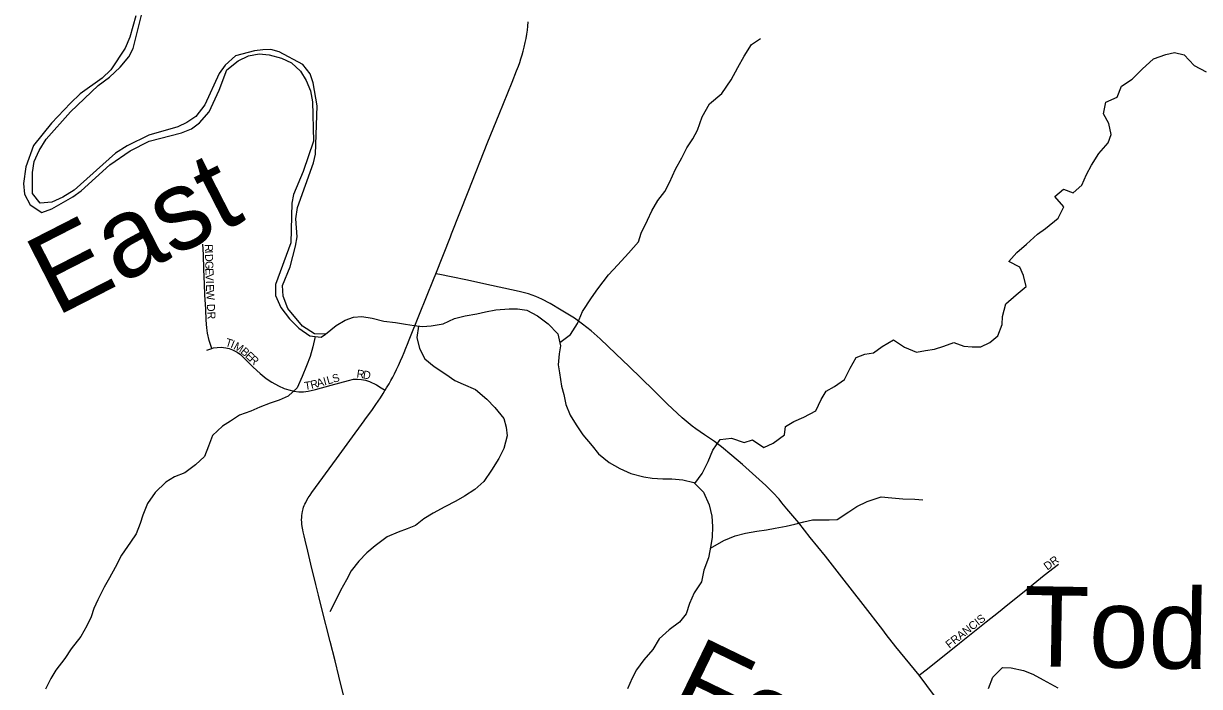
# Model space of a CAD drawing. Extents: x 1442749 to 1756758, y 235267 to 677782.
# Drawn here: x 1558820 to 1566168, y 496421 to 500562 of the extents above; entities that cross this region are included whole.
import ezdxf

# ---------------------------------------------------------------- set-up
doc = ezdxf.new("R2010")
doc.units = 0
for name, color, linetype in [('GM_X_Major_River', 7, 'Continuous'), ('GM_X_Minor_River', 7, 'Continuous'), ('GM_X_Minor_River_Text', 7, 'Continuous'), ('GM_X_State_Route', 7, 'Continuous'), ('GM_X_Township_Road', 7, 'Continuous'), ('GM_X_Township_Subdivision', 7, 'Continuous'), ('GM_X_Township_Subdivision_Text', 7, 'Continuous')]:
    doc.layers.add(name, color=color, linetype=linetype)

msp = doc.modelspace()

# ---------------------------------------------------------------- linework, layer by layer
at = {"layer": 'GM_X_Major_River'}
for points in [[(1559951.9, 500053.5), (1559896.8, 499982), (1559840.2, 499942.7), (1559783.7, 499917.4), (1559602.8, 499863.8), (1559467.7, 499797.4), (1559394.9, 499752.3), (1559135.3, 499521.3), (1559064.6, 499476.2), (1558996.1, 499445), (1558923.9, 499440), (1558874.8, 499500.8), (1558874.7, 499631.1), (1558885.6, 499699.1), (1558916.7, 499768.8), (1558961.8, 499840.4), (1559112.4, 500010.7), (1559287, 500174.7), (1559355.8, 500225.9), (1559422.8, 500289.1), (1559477.8, 500354.5), (1559504.5, 500406.3), (1559572.6, 500680)], [(1559521.5, 500610.5), (1559483.5, 500476.7)], [(1559483.5, 500476.7), (1559454.5, 500407), (1559364.5, 500271.9), (1559311.7, 500220.5), (1559174.1, 500122.1), (1559113.2, 500064.8), (1558995.3, 499940.1)], [(1558995.3, 499940.1), (1558881.1, 499799.3), (1558833.1, 499665.7), (1558819.6, 499561.7), (1558826.6, 499495.4), (1558861.7, 499428.8), (1558933.1, 499381.7), (1558995.5, 499404.9), (1559128.7, 499479.3), (1559179.3, 499516.7), (1559359.8, 499678.6), (1559485.2, 499767.1), (1559604.2, 499827.6), (1559807.2, 499879), (1559869.6, 499904.2), (1559920.2, 499941.6), (1559979.3, 500011), (1560041.3, 500144.5), (1560089.2, 500272.1), (1560160.1, 500329.3), (1560224.6, 500360.5), (1560292.8, 500371.6), (1560354.8, 500366.7), (1560430.6, 500345.7), (1560494.2, 500316.7), (1560549.5, 500263.9), (1560586.7, 500205.2), (1560611.8, 500140.8), (1560624.8, 500072.4), (1560631.3, 499827.8), (1560566.5, 499638.3), (1560506.3, 499492.8), (1560495.5, 499438.8), (1560489.9, 499192.3), (1560394, 498931), (1560395, 498862.8), (1560428, 498788.2), (1560481, 498717.4), (1560540.2, 498658.4), (1560609.6, 498611.4), (1560641.9, 498607.3), (1560679.5, 498602.4), (1560705.8, 498622.1)], [(1560365.3, 500398.6), (1560315.2, 500397.3), (1560263.1, 500392), (1560144.5, 500359.5), (1560079.6, 500302.3), (1560042.8, 500248.7), (1559951.9, 500053.5)], [(1560705.8, 498622.1), (1560637.8, 498623), (1560562.4, 498672.2), (1560471.9, 498781.6), (1560443, 498858.2), (1560438, 498924.4), (1560485.7, 499042), (1560519.6, 499171.9), (1560528.5, 499229.9), (1560522.1, 499342.2), (1560531.1, 499412.2), (1560631.3, 499691.5), (1560644.1, 499745.5), (1560654.5, 500048), (1560630.5, 500190.6), (1560611.3, 500247), (1560564.2, 500305.8), (1560417.2, 500385.9), (1560365.3, 500398.6)]]:
    msp.add_lwpolyline(points, dxfattribs=at)
at = {"layer": 'GM_X_Minor_River'}
for points in [[(1562170.2, 498568.5), (1562237.3, 498619.5), (1562280.4, 498687.1), (1562311.5, 498762.8), (1562368.8, 498848.2), (1562407.6, 498903.8), (1562475, 498991.1), (1562534, 499054.5), (1562599.1, 499127.7), (1562662.2, 499199), (1562679, 499252.9), (1562718.2, 499332.6), (1562745.1, 499392.4), (1562784, 499456), (1562826.9, 499513.5), (1562855.8, 499569.3), (1562893, 499653), (1562934.1, 499722.5), (1562965, 499786.3), (1563001.9, 499841.9), (1563030.7, 499895.6), (1563059.9, 499979.4), (1563105.2, 500061), (1563184.1, 500124.1), (1563241.4, 500209.5), (1563282.6, 500287.1), (1563321.7, 500358.7), (1563368.8, 500430.2), (1563425.4, 500467.6)], [(1563014.6, 497688.9), (1563059.5, 497750.5), (1563098.7, 497826.1), (1563127.8, 497897.9), (1563172.8, 497963.4), (1563243, 497972.5), (1563322.6, 497945.3), (1563374.9, 497960.7), (1563446.3, 497913.6), (1563502.8, 497940.9), (1563575.6, 497992), (1563580.3, 498044.1), (1563632.8, 498075.5), (1563695.3, 498102.7), (1563769.9, 498141.8), (1563803, 498213.5), (1563835.8, 498265.1), (1563886.3, 498294.5), (1563949, 498337.8), (1563984, 498409.5), (1564023, 498475.1), (1564077.4, 498496.4), (1564131.6, 498505.7), (1564184.2, 498545), (1564254.9, 498586.2), (1564324.3, 498541.1), (1564399.9, 498508), (1564456.1, 498519.3), (1564512.3, 498528.6), (1564570.6, 498545.8), (1564633, 498569), (1564694.7, 498546.1), (1564746.7, 498541.4), (1564800.8, 498542.7), (1564857.2, 498570), (1564907.9, 498611.4), (1564934.9, 498681.2), (1564937.7, 498731.3), (1564956.9, 498811.2), (1565021.7, 498866.4), (1565084.6, 498919.7), (1565067.5, 498988.1), (1565044.3, 499040.5), (1564976.7, 499075.5), (1565025.6, 499131), (1565086.4, 499184.3), (1565155.4, 499245.5), (1565205.9, 499280.9), (1565285, 499345.9), (1565320, 499417.6), (1565262.9, 499480.5), (1565317.6, 499527.9), (1565379.4, 499505), (1565432.1, 499552.4), (1565461.1, 499618.2), (1565494, 499677.8), (1565539.1, 499749.4), (1565598.1, 499816.8), (1565614.9, 499868.6), (1565601.9, 499937), (1565568.7, 499997.5), (1565581.8, 500071.5), (1565654.3, 500102.6), (1565681.3, 500170.4), (1565748, 500213.6), (1565809, 500276.9), (1565880, 500342.1), (1565956.5, 500369.1), (1566010.7, 500380.4), (1566072.5, 500365.5), (1566133.6, 500298.6), (1566209.1, 500259.5)], [(1560705.8, 498622.1), (1560772.7, 498675.3), (1560829.2, 498708.6), (1560881.5, 498728), (1560933.7, 498731.3), (1560997.6, 498722.4), (1561071.4, 498703.4), (1561143.3, 498694.4), (1561207.2, 498683.5), (1561261.2, 498674.8), (1561313.1, 498670), (1561367.3, 498673.3), (1561441.5, 498686.4), (1561512.1, 498719.5), (1561578.4, 498736.6), (1561652.6, 498747.6), (1561706.9, 498761), (1561771.1, 498774.1), (1561853.3, 498779), (1561905.3, 498780.3), (1561965.3, 498771.5), (1562030.8, 498736.5), (1562098.2, 498685.5), (1562159.3, 498622.5), (1562174.2, 498548.2), (1562167.5, 498498.1), (1562160.5, 498430.1), (1562167.8, 498379.9), (1562180.6, 498297.5), (1562195.9, 498245.2), (1562209, 498182.9), (1562236, 498116.4), (1562273.2, 498055.7), (1562314.3, 497993), (1562373.4, 497924.1), (1562412.7, 497873.5), (1562480, 497820.4), (1562545.5, 497781.5), (1562615.1, 497750.5), (1562694.9, 497731.3), (1562746.8, 497722.6), (1562814.8, 497717.7), (1562870.9, 497716.9), (1562938.9, 497712), (1563008.7, 497695), (1563067.9, 497634.1), (1563104.8, 497555.4), (1563119.7, 497485.1), (1563124.8, 497420.8), (1563121.8, 497352.7), (1563115.1, 497300.7), (1563100, 497224.8), (1563070.8, 497147), (1563055.7, 497075), (1563010.7, 497005.5), (1562981.7, 496939.7), (1562960.7, 496873.8), (1562917.9, 496822.3), (1562853.2, 496775.1), (1562792.3, 496717.8), (1562751.3, 496652.2), (1562696.3, 496586.8), (1562649.3, 496525.3), (1562622.6, 496473.5), (1562593.6, 496405.8)], [(1561287.6, 498672.4), (1561278.1, 498600.4), (1561293.1, 498532), (1561328.2, 498467.4), (1561385.6, 498420.5), (1561459, 498371.4), (1561514.5, 498332.6), (1561566.2, 498309.8), (1561643.8, 498276.7), (1561714.9, 498215.6), (1561764.2, 498162.8), (1561821.3, 498093.9), (1561834.5, 498039.6), (1561841.8, 497987.4), (1561820.6, 497907.5), (1561789.6, 497843.8), (1561744.5, 497772.2), (1561695.5, 497700.7), (1561640.7, 497651.4), (1561576, 497610.1), (1561521.5, 497578.8), (1561452.9, 497543.7), (1561378.3, 497502.6), (1561321.7, 497467.3), (1561269, 497425.9), (1561216.7, 497404.5), (1561160.3, 497385.3), (1561091.8, 497356.1), (1561016.9, 497299), (1560964.3, 497255.6), (1560915.5, 497204.2), (1560866.5, 497142.7), (1560837.7, 497086.9), (1560800.7, 497021.3), (1560769.7, 496955.6), (1560732.7, 496887.9)], [(1560641.9, 498607.3), (1560626.6, 498543), (1560611.7, 498481.1), (1560588.8, 498423.3), (1560559.8, 498357.5), (1560528.8, 498285.8), (1560474, 498234.4), (1560417.5, 498209.1), (1560361.2, 498189.8), (1560296.8, 498164.6), (1560240.4, 498141.3), (1560169.9, 498116.2), (1560113.4, 498078.9), (1560062.8, 498047.5), (1559999.9, 497988.2), (1559974.9, 497922.4), (1559950, 497856.6), (1559893.2, 497805.3), (1559828.4, 497756), (1559763.9, 497730.8), (1559709.4, 497697.5), (1559642.4, 497632.3), (1559595.3, 497562.8), (1559564.3, 497491), (1559547.5, 497439.1), (1559524.5, 497375.3), (1559487.7, 497321.7), (1559432.5, 497240.2), (1559391.3, 497164.6), (1559356.4, 497099), (1559323.5, 497041.3), (1559284.3, 496961.6), (1559259.5, 496907.8), (1559242.7, 496856), (1559215.9, 496800.2), (1559176.9, 496732.6), (1559117.7, 496655.2), (1559076.8, 496595.6), (1559021.6, 496522.2), (1558990.9, 496470.5), (1558955.9, 496404.8)], [(1563112.1, 497285.6), (1563195.6, 497331.7), (1563266.1, 497362.8), (1563330.4, 497378), (1563402.7, 497391), (1563462.9, 497400.2), (1563517.1, 497409.5), (1563585.3, 497422.6), (1563639.5, 497433.9), (1563695.8, 497449.2), (1563750.1, 497462.5), (1563854.1, 497461.1), (1563904.2, 497464.4), (1563977, 497511.5), (1564027.5, 497544.9), (1564092, 497576.1), (1564178.6, 497605), (1564244.5, 497598.1), (1564314.5, 497593.2), (1564388.5, 497590.2), (1564438.6, 497587.5)], [(1564849.8, 496407.3), (1564876.9, 496479.1), (1564937.8, 496538.4), (1564991.9, 496537.6), (1565067.7, 496520.6), (1565127.4, 496497.7), (1565191, 496462.8), (1565282.3, 496411.4)]]:
    msp.add_lwpolyline(points, dxfattribs=at)
at = {"layer": 'GM_X_State_Route'}
for points in [[(1561486.7, 499229.5), (1561494.5, 499249.1), (1561598.3, 499511.5), (1561721.6, 499822.5), (1561792.2, 499995.7), (1561872.6, 500195.6), (1561900.4, 500265.5), (1561911.7, 500295), (1561920.4, 500319.3), (1561927.3, 500340.6), (1561934.7, 500365.8), (1561941.2, 500389.2), (1561947.7, 500414.8), (1561954.7, 500443), (1561959.9, 500468.2), (1561964.7, 500495.9), (1561968.1, 500521.1), (1561970.7, 500545), (1561973.3, 500571.9)], [(1560948.8, 498080), (1560957.3, 498091.6), (1560976.9, 498119.2), (1560999.8, 498151.3), (1561021.7, 498182.8), (1561035.9, 498203.7), (1561049.3, 498223.4), (1561067.1, 498251.3), (1561077.8, 498269), (1561079.5, 498271.7), (1561088.3, 498286.3), (1561104, 498311.9), (1561115.7, 498332.8), (1561126.5, 498352.7), (1561137.8, 498374.4), (1561150.5, 498400.6), (1561162.1, 498426.1), (1561175.2, 498455.2), (1561187, 498481.5), (1561197.3, 498506.4), (1561209, 498534.6), (1561219, 498559.8), (1561228.9, 498585), (1561293.2, 498746.5), (1561380.7, 498962.5), (1561395.1, 498998.9), (1561486.7, 499229.5)], [(1560860.1, 496198.6), (1560789.6, 496485.4), (1560766.5, 496581), (1560736, 496701.9), (1560684.2, 496905), (1560663, 496991.1), (1560646.5, 497057.9), (1560615.5, 497185.3), (1560595.9, 497265), (1560578.5, 497335), (1560572.5, 497361.4), (1560566.7, 497387), (1560564, 497400.1), (1560562.3, 497410), (1560560.5, 497421.1), (1560558.9, 497434.3), (1560558, 497446.7), (1560557.5, 497462.6), (1560557.9, 497475.6), (1560558.9, 497488.6), (1560560.2, 497501.1), (1560562.3, 497513.8), (1560566.1, 497529.4), (1560569.7, 497540.2), (1560573.8, 497550.3), (1560577.9, 497560.2), (1560583, 497570.8), (1560590.9, 497584.9), (1560599, 497599), (1560609.8, 497615.2), (1560620.7, 497631.6), (1560774.7, 497843.4), (1560858.5, 497956.6), (1560948.8, 498080)]]:
    msp.add_lwpolyline(points, dxfattribs=at)
at = {"layer": 'GM_X_Township_Road'}
for points in [[(1564415.2, 496491.2), (1564271.3, 496669.1), (1564210.3, 496746.3), (1564188.1, 496774.4), (1564065.5, 496933.8), (1563932.4, 497104.6), (1563830.6, 497233.9), (1563736, 497350.5), (1563664.4, 497442.3), (1563590.1, 497530.4), (1563558, 497568), (1563540.5, 497590), (1563502.1, 497633.4), (1563457.8, 497676.8), (1563396.5, 497733.2), (1563313.1, 497807.1), (1563246.6, 497863.1), (1563181.7, 497916.8), (1563156.5, 497936.1), (1563137.2, 497950.2), (1563073.9, 497993.1), (1563019.7, 498029.6), (1562997.1, 498047.3), (1562935.5, 498098), (1562844.5, 498183.3), (1562755.7, 498270.8), (1562603, 498419.6), (1562520.3, 498499.2), (1562422.9, 498591.9), (1562366.7, 498642), (1562312.7, 498684.5), (1562262, 498720.4), (1562179.8, 498770.5), (1562111.4, 498812.8), (1562059.3, 498840.2), (1562020.4, 498857), (1561974.1, 498872.8), (1561917.3, 498888.2), (1561696.7, 498936.8), (1561594, 498958.3), (1561491.1, 498978.7), (1561421.3, 498993.4), (1561395.1, 498998.9)], [(1564897.4, 495921.6), (1564871.2, 495939.5), (1564808.7, 495986.9), (1564780.1, 496008.9), (1564698.1, 496074.6), (1564679.1, 496093.2), (1564660.2, 496116.2), (1564636.2, 496151.8), (1564612.4, 496194.9), (1564578.2, 496258.2), (1564543, 496317.1), (1564511.8, 496363), (1564415.2, 496491.2)]]:
    msp.add_lwpolyline(points, dxfattribs=at)
at = {"layer": 'GM_X_Township_Subdivision'}
for points in [[(1559996.2, 498531.9), (1559987.6, 498557.1), (1559978.8, 498582.7), (1559969.8, 498627.2), (1559964.8, 498660), (1559961.6, 498709.4), (1559959.2, 498778.4), (1559953.3, 498866.9), (1559949.8, 498935.7), (1559946.6, 499025.5), (1559943.3, 499120), (1559940.4, 499183.2)], [(1559965.1, 498520.7), (1559983, 498528), (1559996.2, 498531.9)], [(1559996.2, 498531.9), (1560007.5, 498535.2), (1560029.5, 498538.7), (1560055, 498539.7), (1560083.6, 498536.8), (1560105.2, 498531.7), (1560126, 498523.5), (1560154.3, 498508.5), (1560175, 498493.7), (1560203.1, 498467), (1560254.2, 498416.2), (1560297.5, 498375.9), (1560336.1, 498345.1), (1560371.7, 498321.3), (1560412.1, 498298.8), (1560448.4, 498282.5), (1560476.8, 498272.9), (1560509.1, 498265.3), (1560539, 498261.6), (1560569.1, 498261.7), (1560598.8, 498265.2), (1560644.1, 498275.1), (1560742.1, 498302.8), (1560849.3, 498333), (1560880.7, 498339.6), (1560906.2, 498341.2), (1560931.7, 498339.2), (1560956.7, 498333.9), (1560980.8, 498325.5), (1561024.6, 498304), (1561055.1, 498286), (1561079.5, 498271.7)], [(1564415.2, 496491.2), (1564468.4, 496531.4), (1564668, 496690.7), (1564834.4, 496823.6), (1564911.5, 496884.8), (1564970.2, 496932.1), (1565051.7, 496997.8), (1565105, 497041.4), (1565196.5, 497115.9), (1565287.7, 497184.3)]]:
    msp.add_lwpolyline(points, dxfattribs=at)

# ---------------------------------------------------------------- texts
at = {"layer": 'GM_X_Minor_River_Text'}
for s, height, rotation, p in [('East', 500.01, 27.08228, (1559023.6, 498729.3)), ('Todds', 499.98, 359.0438, (1565065.7, 496548.4)), ('Fork', 499.96, 334.17159, (1562831.7, 496289.3))]:
    msp.add_text(s, height=height, rotation=rotation, dxfattribs=at).set_placement(p)
at = {"layer": 'GM_X_Township_Subdivision_Text'}
for s, rotation, p in [('R', 271.7004, (1559951.8, 499183)), ('I', 271.68341, (1559953, 499143.5)), ('D', 271.69472, (1559953.6, 499121.5)), ('G', 271.69472, (1559954.9, 499077.5)), ('E', 271.70812, (1559956.2, 499033.5)), ('V', 271.69434, (1559957.3, 498998.3)), ('I', 271.71593, (1559958.6, 498954.3)), ('E', 271.69434, (1559959.2, 498932.3)), ('W', 274.41967, (1559960.4, 498894.6)), ('DR', 273.01099, (1559965, 498809.3)), ('T', 343.11624, (1560076.8, 498549.5)), ('I', 337.85765, (1560109.3, 498539.7)), ('M', 329.82813, (1560128, 498532.2)), ('B', 318.14459, (1560171.5, 498507.3)), ('E', 317.164, (1560200.8, 498481)), ('R', 317.45228, (1560226.9, 498456.9)), ('I', 15.26087, (1560700.2, 498300.9)), ('L', 16.23816, (1560722.3, 498306.9)), ('S', 17.274, (1560757, 498317)), ('R', 351.66556, (1560898.5, 498351.7)), ('D', 350.49276, (1560937.4, 498346)), ('T', 8.05862, (1560577.9, 498272.8)), ('R', 14.90333, (1560619.1, 498279)), ('A', 15.29405, (1560657.7, 498289.3)), ('DR', 36.25541, (1565216.9, 497144.4)), ('FRANCIS', 38.21527, (1564605.2, 496656))]:
    msp.add_text(s, height=50, rotation=rotation, dxfattribs=at).set_placement(p)

doc.saveas('drawing.dxf')
